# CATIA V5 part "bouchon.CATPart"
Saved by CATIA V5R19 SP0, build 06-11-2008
Part number: bouchon
Bounding box of the stored display mesh (mm): x 0 to 8.112, y -4 to 4, z -4 to 4
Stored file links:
  I:\mediator\bouchon.CATPart
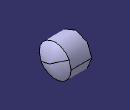
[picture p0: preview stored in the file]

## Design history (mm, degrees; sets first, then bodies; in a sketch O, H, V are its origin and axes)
Body1 (main body)
  Sketch1 on yz-plane, origin (0, 0, 0), H (0, 1, 0), V (0, 0, 1)
    circle A1 centre (0, 0) radius 1.6
    radius A1 = 1.6
  Pad1: profile Sketch1, direction (1, 0, 0), length 1.5
  Sketch2 on end face of Pad1, origin (1.5, 0, 0), H (0, 1, 0), V (0, 0, 1)
    circle A1 centre (0, 0) radius 4
    radius A1 = 4
  Pad2: profile Sketch2, direction (1, 0, 0), length 5.176
  Sketch3 on xy-plane, origin (0, 0, 0), H (1, 0, 0), V (0, 1, 0)
    point P1 (6.676, 4)
    arc A1 centre (1.4088, -0.1494) radius 6.7053 from (6.676, 4) to (8.1124, 0) cw
    point P3 (8.1124, 0)
    line L1 (6.676, 4) -> (6.676, 0)
    point P4 (6.676, 0)
    line L2 (6.676, 0) -> (8.1124, 0)
    reference projected line E1 (6.676, 4) -> (6.676, -4) from edge [face of Pad2 from Sketch2.A1 | end face of Pad2]
    reference projected line E2 through (0, 0) direction (1, 0) from axis of face of Pad2 from Sketch2.A1
    distance L1 E1 = 0
    distance P1 E2 = 4
    coincidence: P3 H, P4 H
    vertical: L1 V
    horizontal: L2 H
  Shaft1: profile Sketch3, axis Sketch3.L2, angle 360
